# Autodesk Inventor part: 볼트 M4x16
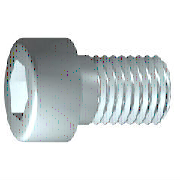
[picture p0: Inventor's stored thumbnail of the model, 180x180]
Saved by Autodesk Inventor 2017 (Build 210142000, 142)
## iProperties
Created: 2012-02
Part Number: 볼트 M4x16
Material: 스테인리스강
Description: 6각 소켓 머리 캡 나사
Document SubType Name: Modeling
Standard: ISO 4762
Designer: mduedu
Standard Revision: Fourth edition 2004-03-01
Standards Organization: ISO
Language: ko-KR
Size Designation: M4 x 16
Categories: <MemberInstance><Categories><Category DisplayName="조임쇠" InternalName="e4da775c-781d-43d5-af7c-5136215cf5a6" Mnemonic="FSTN"><Category DisplayName="볼트" InternalN
Density: 7.75 g/cm^3
Appearance: 반광택
IsCustomPart: 0
Author: mduedu
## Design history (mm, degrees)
sketch "스케치1"
  geometry: L1 (-1, 0)-(16, 0); L2 (16, 0)-(16, 2); L3 (16, 2)-(1.75, 2); L4 (1.75, 2)-(1.32, 2); L5 (1.32, 2)-(0, 2); L6 (0, 2)-(0, 3.5); L7 (0, 3.5)-(-4, 3.5); L8 (-4, 3.5)-(-4, 1.732); L9 (-4, 1.732)-(-2, 1.732); L10 (-2, 1.732)-(-1, 0); L11 (-8, 0)-(20, 0) reference; L12 (0, -0.7)-(0, 4.2) reference; L13 (1.75, 2)-(0, 2)
  constraints: 22 end point, 6 parallel, 2 collinear, 2 perpendicular, 1 horizontal, 1 point on line
  dimensions: "d1" = 14.25 distance from line of L3.end L2 (= GEL); "d2" = 0.42952 distance of L4.end L3.end (computed from GAL); "d3" = 4 distance between parallel lines of L8 L6 (= KOH); "d4" = 2 distance of L8.end L9.end (= INTI); "d5" = 60 deg angle of L10 L1; "d6" = 4 diameter of L3 L1 (= GD); "d7" = 4 diameter of L5 L1 (= BDM); "d8" = 3.4641 diameter of L9 L1 (= 1.1547 x SW); "d9" = 7 diameter of L7 L1 (= KOD); "d26" = 16 distance between parallel lines of L12 L2 (= NLG)
revolve "본체" sketch "스케치1" stored, may be unused: angle "d10" = 90 deg
sketch "스케치2"
  geometry: L1 (0, -4.9)-(0, 4.9) reference; L2 (-4.9, 0)-(4.9, 0) reference; L3 (1.732, 0)-(0.866, -1.5); L4 (0.866, -1.5)-(-0.866, -1.5); L5 (-0.866, -1.5)-(-1.732, 0); L6 (-1.732, 0)-(-0.866, 1.5); L7 (-0.866, 1.5)-(0.866, 1.5); L8 (0.866, 1.5)-(1.732, 0); 2 further points
  constraints: 12 end point, 1 coincident, 1 horizontal alignment, 1 point on line, 12 other
extrude "슬롯" join sketch "스케치2" stored distance "d11" = 10; taper "d12" = 0 deg
workplane "Work Plane1"
fillet "Fillet2" dims "d30" = 0.1 (= R)
body "Solid1"
fillet "모깎기1" dims "d17" = 0.4 (= RR)
feature "스레드" dims "d13" = 14.25 (= GEL), "d14" = 0
chamfer "모따기1" distance "d15" = 0.42941 (= -0.5 x SPD + 0.5 x GD); stored, may be unused: second distance "d16" = 0.42941 (= GUL), angle "d27" = 45 deg
other parameters: "GD" = 4 [user parameter; used in 2 equation terms], "NLG" = 16 [user parameter; used in 1 equation term], "GEL" = 14.25 [user parameter; used in 2 equation terms], "KOD" = 7 [user parameter; used in 1 equation term], "KOH" = 4 [user parameter; used in 1 equation term], "INTI" = 2 [user parameter; used in 1 equation term], "GAL" = 0.42941 (= 0.61345 x PTC) [user parameter; used in 1 equation term], "GUL" = 0.42941 (= 0.61345 x PTC) [user parameter; used in 1 equation term], "BDM" = 4 (= NND) [user parameter; used in 1 equation term], "SW" = 3 [user parameter; used in 2 equation terms], "RR" = 0.4 [user parameter; used in 1 equation term], "SPD" = 3.14117 (= NND - 1.2269 x PTC) [user parameter; used in 1 equation term], "d19" = 0, "d28" = 0, "d29" = 0, "R" = 0.1 [user parameter; used in 1 equation term], "TOA" = 30 deg [user parameter], "GD1" = 3.14117 (= THREADDIA - 1.2269 x PTC) [user parameter], "THREADDIA" = 4 [user parameter; used in 1 equation term], "FAWI" = 45 deg [user parameter], "TPU" = 14.28571 (computed from PTC) [user parameter], "PTC" = 0.7 [user parameter; used in 5 equation terms], "NND" = 4 [user parameter; used in 2 equation terms], "E0" = 3.465 (= 1.155 x SW) [user parameter]
